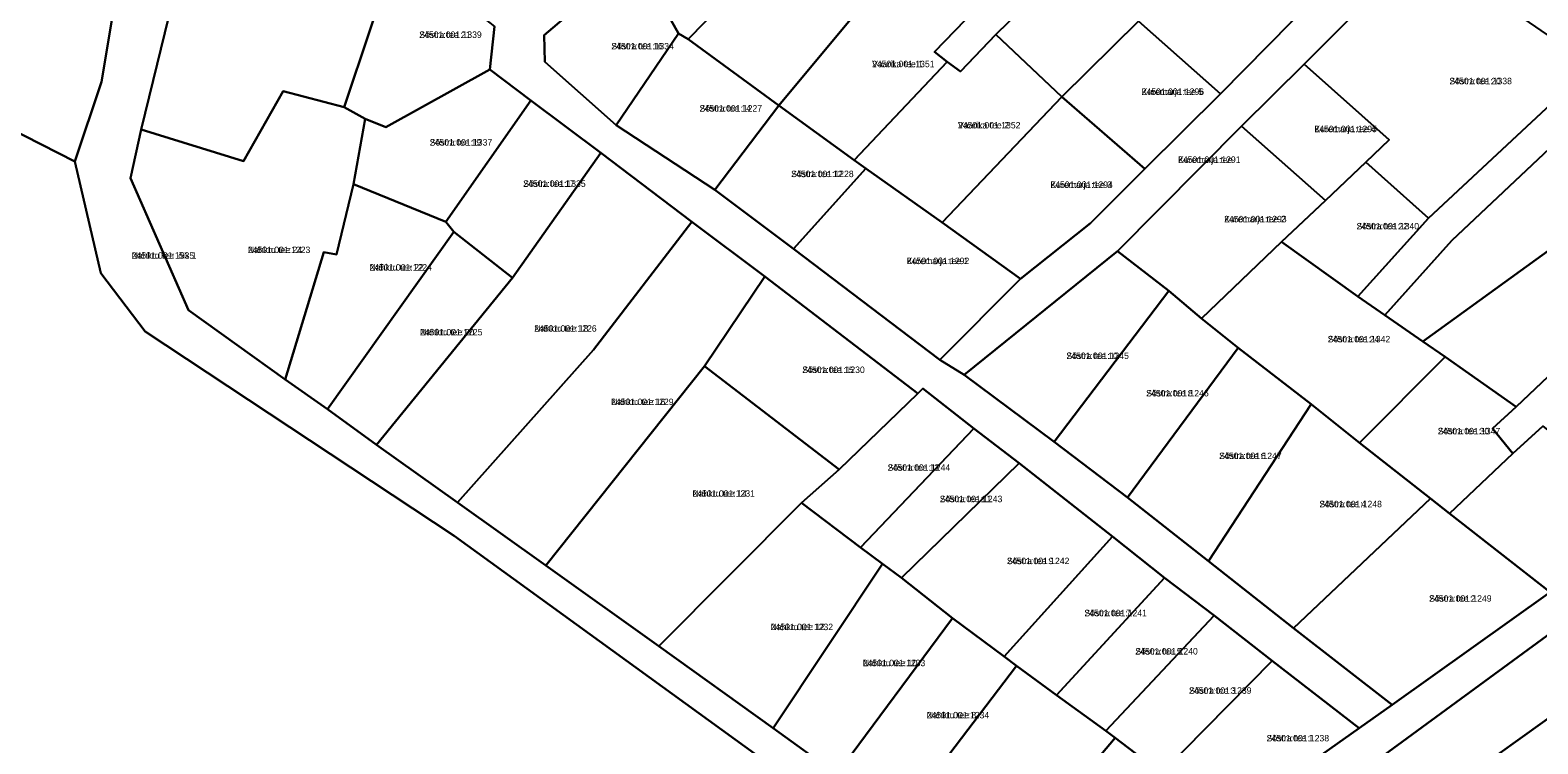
# Model space of a CAD drawing. Extents: x 551291 to 575799, y 6581704 to 6610137.
# Drawn here: x 558893.3 to 559243.4, y 6593771.7 to 6593937.5 of the extents above; entities that cross this region are included whole.
import ezdxf

# ---------------------------------------------------------------- set-up
doc = ezdxf.new("R2010")
doc.units = 0
for name, color, linetype in [('L_AADRESS', 7, 'Continuous'), ('PIIR', 7, 'Continuous'), ('TUNNUS', 7, 'Continuous')]:
    doc.layers.add(name, color=color, linetype=linetype)

msp = doc.modelspace()

# ---------------------------------------------------------------- linework, layer by layer
at = {"layer": 'PIIR'}
for points in [[(558177.52, 6592770.55), (558170.99, 6592891.67), (558187.73, 6592959.33), (558210.3, 6593010.98), (558251.88, 6593067.47), (558331.23, 6593148.23), (558500.98, 6593273.8), (558515.98, 6593265.59), (558725.44, 6593417.8), (558892.15, 6593539.14), (558974.44, 6593599.03), (559131.4, 6593713.23), (559146.17, 6593723.99), (559299.06, 6593836.09), (559444.58, 6594136.67), (559447.22, 6594142.1), (559464.89, 6594178.58), (559481.53, 6594212.94), (559484.05, 6594218.05)], [(559107.63, 6593735.97), (558991.73, 6593820.06), (558919.99, 6593867.54), (558909.72, 6593881.1), (558903.67, 6593906.99), (558909.88, 6593925.54), (558928.3, 6594035.88)], [(558934.7, 6593978.41), (558919.07, 6593914.47), (558916.59, 6593903.1), (558930.04, 6593872.48), (558952.49, 6593856.38), (558962.36, 6593849.43), (558973.75, 6593841.17), (558992.51, 6593827.76), (559013.01, 6593813.13), (559039.28, 6593794.38), (559065.81, 6593775.35), (559080.62, 6593764.69)], [(559033.92, 6593954.49), (559012.67, 6593936.38), (559012.85, 6593930.16), (559029.34, 6593915.49), (559052.29, 6593900.45), (559070.55, 6593886.69), (559104.5, 6593860.91), (559110.15, 6593857.43), (559131.09, 6593841.89), (559148.09, 6593828.92), (559166.9, 6593814.11), (559186.62, 6593798.55), (559209.55, 6593780.73), (559201.87, 6593775.34), (559181.7, 6593790.95), (559168.21, 6593801.51), (559156.74, 6593810.3), (559144.63, 6593819.85), (559122.96, 6593836.94), (559112.43, 6593845), (559100.6, 6593854.27), (559099.42, 6593853.14), (559063.88, 6593880.32), (559046.92, 6593892.99), (559025.78, 6593908.99), (559009.53, 6593921.19), (559000.02, 6593928.41), (559001.11, 6593938.37)], [(559260.76, 6593923.79), (559223.41, 6593888.67), (559207.9, 6593871.33), (559201.59, 6593875.63), (559218.03, 6593893.87), (559254.43, 6593927.81)], [(559547.24, 6593894.87), (559454.05, 6593884.92), (559412.21, 6593875.63), (559395.77, 6593868.26), (559389.79, 6593868.69), (559358.56, 6593852.25), (559312.56, 6593828.02), (559299.35, 6593813.89), (559293.37, 6593811.67), (559271.2, 6593795.97), (559249.66, 6593780.34), (559228.92, 6593765.5)], [(559244.59, 6593845.49), (559237.57, 6593839.14), (559232.88, 6593844.98), (559238.38, 6593849.98), (559275.2, 6593884.95)]]:
    msp.add_lwpolyline(points, dxfattribs=at)
for points in [[(558860.47, 6593928.98), (558870.47, 6593993.01), (558894.45, 6594145.91), (558945.47, 6594137.86), (558940.29, 6594107.58), (558928.3, 6594035.88), (558909.88, 6593925.54), (558903.67, 6593906.99)], [(559171.21, 6593753.59), (559201.87, 6593775.34), (559209.55, 6593780.73), (559246.25, 6593806.94), (559271.02, 6593824.58), (559293.51, 6593840.52), (559316.24, 6593887.55), (559335.18, 6593926.77), (559358.82, 6593975.74), (559369.18, 6593996.97), (559372.27, 6594003.33), (559388.13, 6594036.07), (559408, 6594077.05), (559411.94, 6594085.21), (559438.12, 6594139.38), (559444.58, 6594136.67), (559299.06, 6593836.09), (559146.17, 6593723.99), (559138.1, 6593729.93)], [(559106.24, 6593930.2), (559103.32, 6593932.48), (559110.45, 6593939.88), (559127.58, 6593956.67), (559162.37, 6593991.17), (559168.66, 6593986.87), (559134.95, 6593953.59), (559117.57, 6593936.55), (559109.37, 6593927.89)], [(558942.85, 6593907.12), (558919.07, 6593914.47), (558934.7, 6593978.41), (558939.73, 6593986.47), (558978.48, 6593956.26), (558966.22, 6593919.61), (558952.05, 6593923.32)], [(559043.84, 6593936.76), (559033.92, 6593954.49), (559044.72, 6593960.18), (559052.76, 6593968.98), (559065.7, 6593955.46), (559046.11, 6593935.41)], [(559067.14, 6593920.06), (559046.11, 6593935.41), (559065.7, 6593955.46), (559078.07, 6593967.3), (559083.68, 6593961.87), (559093.75, 6593952.11)], [(559110.15, 6593857.43), (559104.5, 6593860.91), (559123.24, 6593879.77), (559139.5, 6593892.66), (559152.11, 6593905.34), (559169.67, 6593922.74), (559186.26, 6593939.52), (559207.3, 6593960.67), (559215.23, 6593955.78), (559189.1, 6593929.66), (559174.61, 6593915.19), (559145.8, 6593886.2)], [(558971.11, 6593916.96), (558966.22, 6593919.61), (558978.48, 6593956.26), (559001.11, 6593938.37), (559000.02, 6593928.41), (558975.92, 6593914.98)], [(559169.67, 6593922.74), (559150.68, 6593939.65), (559167.13, 6593956.42), (559186.26, 6593939.52)], [(559208.87, 6593912.05), (559189.1, 6593929.66), (559215.23, 6593955.78), (559217.11, 6593956.06), (559254.15, 6593930.55), (559254.43, 6593927.81), (559218.03, 6593893.87), (559203.42, 6593906.86)], [(559012.85, 6593930.16), (559012.67, 6593936.38), (559033.92, 6593954.49), (559043.84, 6593936.76), (559029.34, 6593915.49)], [(559084.64, 6593907.29), (559067.14, 6593920.06), (559093.75, 6593952.11), (559110.45, 6593939.88), (559103.32, 6593932.48), (559106.24, 6593930.2)], [(559132.85, 6593922), (559117.57, 6593936.55), (559134.95, 6593953.59), (559150.68, 6593939.65)], [(559152.11, 6593905.34), (559132.85, 6593922), (559150.68, 6593939.65), (559169.67, 6593922.74)], [(559052.29, 6593900.45), (559029.34, 6593915.49), (559043.84, 6593936.76), (559046.11, 6593935.41), (559067.14, 6593920.06)], [(559087.36, 6593905.41), (559084.64, 6593907.29), (559106.24, 6593930.2), (559109.37, 6593927.89), (559117.57, 6593936.55), (559132.85, 6593922), (559105.06, 6593892.83)], [(558848.05, 6593879.64), (558864.79, 6593918.03), (558860.47, 6593928.98), (558903.67, 6593906.99), (558909.72, 6593881.1), (558919.99, 6593867.54), (558991.73, 6593820.06), (559107.63, 6593735.97), (559131.4, 6593713.23), (558974.44, 6593599.03), (558967.52, 6593607.41), (558955.89, 6593623.55), (558983.88, 6593649.3), (558928.27, 6593700.28), (558901.17, 6593726.09), (558876.72, 6593752.5), (558850.2, 6593776.1), (558837.39, 6593784.85), (558822.68, 6593787.24), (558821.73, 6593800.8), (558836.41, 6593829.86), (558843.39, 6593830.35), (558853.81, 6593877.09)], [(558968.36, 6593901.73), (558971.11, 6593916.96), (558975.92, 6593914.98), (559000.02, 6593928.41), (559009.53, 6593921.19), (558989.8, 6593893.02)], [(559194.08, 6593897.98), (559174.61, 6593915.19), (559189.1, 6593929.66), (559208.87, 6593912.05), (559203.42, 6593906.86)], [(558916.59, 6593903.1), (558919.07, 6593914.47), (558942.85, 6593907.12), (558952.05, 6593923.32), (558966.22, 6593919.61), (558971.11, 6593916.96), (558968.36, 6593901.73), (558964.46, 6593885.38), (558961.52, 6593885.91), (558952.49, 6593856.38), (558930.04, 6593872.48)], [(559216.68, 6593865.19), (559207.9, 6593871.33), (559223.41, 6593888.67), (559260.76, 6593923.79), (559263.77, 6593924.11), (559292.88, 6593904.11), (559292.93, 6593901.44), (559275.2, 6593884.95), (559259.81, 6593896.4)], [(558991.69, 6593890.68), (558989.8, 6593893.02), (559009.53, 6593921.19), (559025.78, 6593908.99), (559005.3, 6593880.01)], [(559070.55, 6593886.69), (559052.29, 6593900.45), (559067.14, 6593920.06), (559084.64, 6593907.29), (559087.36, 6593905.41)], [(559123.24, 6593879.77), (559105.06, 6593892.83), (559132.85, 6593922), (559152.11, 6593905.34), (559139.5, 6593892.66)], [(559157.7, 6593876.92), (559145.8, 6593886.2), (559174.61, 6593915.19), (559194.08, 6593897.98), (559183.87, 6593888.33), (559165.3, 6593870.56)], [(558992.51, 6593827.76), (558973.75, 6593841.17), (559005.3, 6593880.01), (559025.78, 6593908.99), (559046.92, 6593892.99), (559024.1, 6593863.28)], [(559201.59, 6593875.63), (559183.87, 6593888.33), (559194.08, 6593897.98), (559203.42, 6593906.86), (559218.03, 6593893.87)], [(559104.5, 6593860.91), (559070.55, 6593886.69), (559087.36, 6593905.41), (559105.06, 6593892.83), (559123.24, 6593879.77)], [(558962.36, 6593849.43), (558952.49, 6593856.38), (558961.52, 6593885.91), (558964.46, 6593885.38), (558968.36, 6593901.73), (558989.8, 6593893.02), (558991.69, 6593890.68)], [(559221.9, 6593861.59), (559216.68, 6593865.19), (559259.81, 6593896.4), (559275.2, 6593884.95), (559238.38, 6593849.98)], [(559013.01, 6593813.13), (558992.51, 6593827.76), (559024.1, 6593863.28), (559046.92, 6593892.99), (559063.88, 6593880.32), (559049.86, 6593859.48)], [(558973.75, 6593841.17), (558962.36, 6593849.43), (558991.69, 6593890.68), (559005.3, 6593880.01)], [(559173.82, 6593863.75), (559165.3, 6593870.56), (559183.87, 6593888.33), (559201.59, 6593875.63), (559207.9, 6593871.33), (559216.68, 6593865.19), (559221.9, 6593861.59), (559201.95, 6593841.65), (559190.73, 6593850.61)], [(559131.09, 6593841.89), (559110.15, 6593857.43), (559145.8, 6593886.2), (559157.7, 6593876.92)], [(559081.18, 6593835.41), (559049.86, 6593859.48), (559063.88, 6593880.32), (559099.42, 6593853.14)], [(559148.09, 6593828.92), (559131.09, 6593841.89), (559157.7, 6593876.92), (559165.3, 6593870.56), (559173.82, 6593863.75)], [(559166.9, 6593814.11), (559148.09, 6593828.92), (559173.82, 6593863.75), (559190.73, 6593850.61)], [(559218.47, 6593828.73), (559201.95, 6593841.65), (559221.9, 6593861.59), (559238.38, 6593849.98), (559232.88, 6593844.98), (559237.57, 6593839.14), (559222.88, 6593825.25)], [(559039.28, 6593794.38), (559013.01, 6593813.13), (559049.86, 6593859.48), (559081.18, 6593835.41), (559072.44, 6593827.72)], [(559086.12, 6593817.3), (559072.44, 6593827.72), (559081.18, 6593835.41), (559099.42, 6593853.14), (559100.6, 6593854.27), (559112.43, 6593845)], [(559186.62, 6593798.55), (559166.9, 6593814.11), (559190.73, 6593850.61), (559201.95, 6593841.65), (559218.47, 6593828.73)], [(559091.2, 6593813.54), (559086.12, 6593817.3), (559112.43, 6593845), (559122.96, 6593836.94), (559095.6, 6593810.3)], [(559246.25, 6593806.94), (559222.88, 6593825.25), (559237.57, 6593839.14), (559244.59, 6593845.49), (559271.02, 6593824.58)], [(559107.46, 6593800.9), (559095.6, 6593810.3), (559122.96, 6593836.94), (559144.63, 6593819.85), (559119.48, 6593792.03)], [(559209.55, 6593780.73), (559186.62, 6593798.55), (559218.47, 6593828.73), (559222.88, 6593825.25), (559246.25, 6593806.94)], [(559065.81, 6593775.35), (559039.28, 6593794.38), (559072.44, 6593827.72), (559086.12, 6593817.3), (559091.2, 6593813.54)], [(559122.37, 6593789.82), (559119.48, 6593792.03), (559144.63, 6593819.85), (559156.74, 6593810.3), (559131.65, 6593783.04)], [(559080.62, 6593764.69), (559065.81, 6593775.35), (559091.2, 6593813.54), (559095.6, 6593810.3), (559107.46, 6593800.9)], [(559143.09, 6593774.7), (559131.65, 6593783.04), (559156.74, 6593810.3), (559168.21, 6593801.51)], [(559095.34, 6593754.29), (559080.62, 6593764.69), (559107.46, 6593800.9), (559119.48, 6593792.03), (559122.37, 6593789.82)], [(559145.23, 6593773.06), (559143.09, 6593774.7), (559168.21, 6593801.51), (559181.7, 6593790.95), (559156.03, 6593764.89)], [(559171.21, 6593753.59), (559156.03, 6593764.89), (559181.7, 6593790.95), (559201.87, 6593775.34)], [(559116.5, 6593739), (559095.34, 6593754.29), (559122.37, 6593789.82), (559131.65, 6593783.04), (559143.09, 6593774.7), (559145.23, 6593773.06)], [(559228.92, 6593765.5), (559249.66, 6593780.34), (559256, 6593773.68), (559260.03, 6593769.65), (559238.81, 6593754.43), (559235.7, 6593757.89)], [(559125.35, 6593732.76), (559116.5, 6593739), (559145.23, 6593773.06), (559156.03, 6593764.89)]]:
    msp.add_lwpolyline(points, close=True, dxfattribs=at)

# ---------------------------------------------------------------- texts
at = {"layer": 'L_AADRESS'}
for s, p in [('Sõstra tee 21', (558983.66, 6593935.73)), ('Sõstra tee 16', (559028.26, 6593933.06)), ('Vaarika tee 1', (559088.8, 6593928.92)), ('Kuremarja tee 5', (559151.39, 6593922.49)), ('Sõstra tee 20', (559222.87, 6593924.96)), ('Sõstra tee 14', (559048.75, 6593918.61)), ('Vaarika tee 2', (559108.75, 6593914.69)), ('Kuremarja tee 4', (559191.52, 6593913.82)), ('Sõstra tee 19', (558986.09, 6593910.71)), ('Kuremarja tee', (559159.86, 6593906.69)), ('Sõstra tee 17', (559007.79, 6593901.12)), ('Sõstra tee 12', (559070.02, 6593903.38)), ('Kuremarja tee 3', (559130.21, 6593900.88)), ('Kuremarja tee 2', (559170.56, 6593892.88)), ('Sõstra tee 22', (559201.31, 6593891.24)), ('Nahkru tee lõik 1', (558916.87, 6593884.42)), ('Nahkru tee 24', (558943.85, 6593885.73)), ('Kuremarja tee 1', (559096.86, 6593883.16)), ('Nahkru tee 22', (558972.09, 6593881.66)), ('Nahkru tee 20', (558983.83, 6593866.6)), ('Nahkru tee 18', (559010.34, 6593867.47)), ('Sõstra tee 24', (559194.62, 6593864.99)), ('Sõstra tee 10', (559133.93, 6593861.12)), ('Sõstra tee 15', (559072.6, 6593857.87)), ('Sõstra tee 8', (559152.46, 6593852.42)), ('Nahkru tee 16', (559028.2, 6593850.42)), ('Sõstra tee 30', (559220.17, 6593843.62)), ('Sõstra tee 6', (559169.41, 6593837.87)), ('Sõstra tee 13', (559092.43, 6593835.15)), ('Nahkru tee 14', (559047.09, 6593829.12)), ('Sõstra tee 11', (559104.54, 6593827.85)), ('Sõstra tee 4', (559192.68, 6593826.67)), ('Sõstra tee 9', (559120.12, 6593813.45)), ('Sõstra tee 2', (559218.15, 6593804.73)), ('Sõstra tee 7', (559138.11, 6593801.35)), ('Nahkru tee 12', (559065.24, 6593798.12)), ('Sõstra tee 5', (559149.93, 6593792.45)), ('Nahkru tee 10', (559086.64, 6593789.74)), ('Sõstra tee 3', (559162.4, 6593783.33)), ('Nahkru tee 8', (559101.49, 6593777.62)), ('Sõstra tee 1', (559180.42, 6593772.27))]:
    msp.add_text(s, height=1.5, dxfattribs=at).set_placement(p)
at = {"layer": 'TUNNUS'}
for s, p in [('24501:001:1339', (558983.66, 6593935.73)), ('24501:001:1334', (559028.26, 6593933.06)), ('24501:001:1351', (559088.8, 6593928.92)), ('24501:001:1296', (559151.39, 6593922.49)), ('24501:001:1338', (559222.87, 6593924.96)), ('24501:001:1227', (559048.75, 6593918.61)), ('24501:001:1352', (559108.75, 6593914.69)), ('24501:001:1295', (559191.52, 6593913.82)), ('24501:001:1337', (558986.09, 6593910.71)), ('24501:001:1291', (559159.86, 6593906.69)), ('24501:001:1335', (559007.79, 6593901.12)), ('24501:001:1228', (559070.02, 6593903.38)), ('24501:001:1294', (559130.21, 6593900.88)), ('24501:001:1293', (559170.56, 6593892.88)), ('24501:001:1340', (559201.31, 6593891.24)), ('24501:001:1935', (558916.87, 6593884.42)), ('24501:001:1223', (558943.85, 6593885.73)), ('24501:001:1224', (558972.09, 6593881.66)), ('24501:001:1292', (559096.86, 6593883.16)), ('24501:001:1225', (558983.83, 6593866.6)), ('24501:001:1226', (559010.34, 6593867.47)), ('24501:001:1342', (559194.62, 6593864.99)), ('24501:001:1245', (559133.93, 6593861.12)), ('24501:001:1230', (559072.6, 6593857.87)), ('24501:001:1246', (559152.46, 6593852.42)), ('24501:001:1229', (559028.2, 6593850.42)), ('24501:001:1347', (559220.17, 6593843.62)), ('24501:001:1247', (559169.41, 6593837.87)), ('24501:001:1244', (559092.43, 6593835.15)), ('24501:001:1231', (559047.09, 6593829.12)), ('24501:001:1243', (559104.54, 6593827.85)), ('24501:001:1248', (559192.68, 6593826.67)), ('24501:001:1242', (559120.12, 6593813.45)), ('24501:001:1249', (559218.15, 6593804.73)), ('24501:001:1241', (559138.11, 6593801.35)), ('24501:001:1232', (559065.24, 6593798.12)), ('24501:001:1240', (559149.93, 6593792.45)), ('24501:001:1233', (559086.64, 6593789.74)), ('24501:001:1239', (559162.4, 6593783.33)), ('24501:001:1234', (559101.49, 6593777.62)), ('24501:001:1238', (559180.42, 6593772.27))]:
    msp.add_text(s, height=1.5, dxfattribs=at).set_placement(p)

doc.saveas('drawing.dxf')
